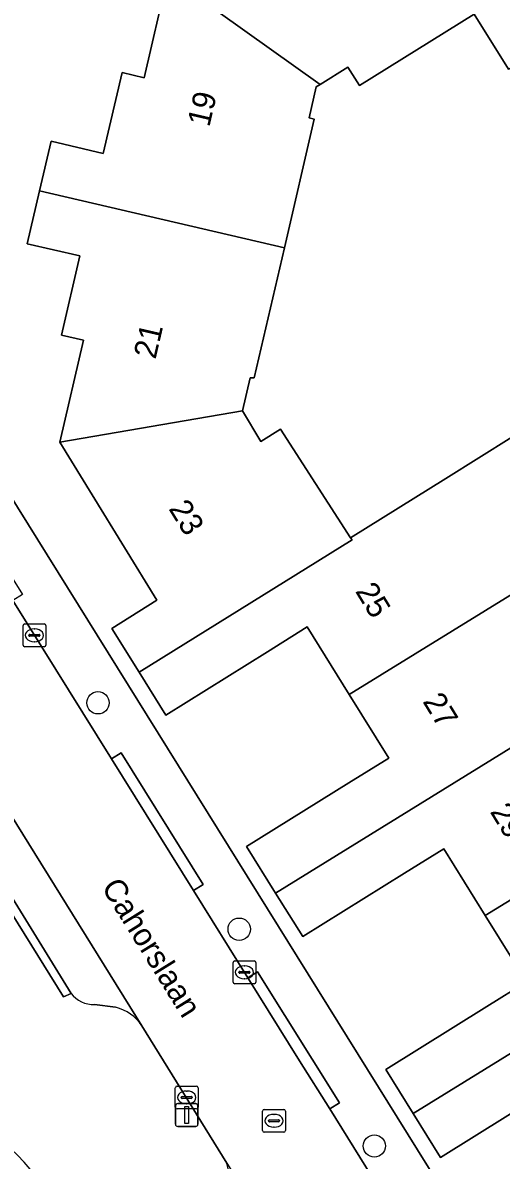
# Model space of a CAD drawing. Extents: x 157767 to 159172, y 387839 to 389425.
# Drawn here: x 158446.08 to 158467.07, y 387924.96 to 387974.82 of the extents above; entities that cross this region are included whole.
import ezdxf

# ---------------------------------------------------------------- set-up
doc = ezdxf.new("R2010")
doc.units = 0
for name, color, linetype in [('IMGEO_Boom', 7, 'Continuous'), ('IMGEO_Erf', 7, 'Continuous'), ('IMGEO_Groenvoorziening', 7, 'Continuous'), ('IMGEO_Kolk', 7, 'Continuous'), ('IMGEO_Lichtmast', 7, 'Continuous'), ('IMGEO_Openbare_ruimte_label', 7, 'Continuous'), ('IMGEO_Pand', 7, 'Continuous'), ('IMGEO_Pand_nummerreeks', 7, 'Continuous'), ('IMGEO_Parkeervlak_open', 7, 'Continuous'), ('IMGEO_Rijbaan_lokaal_open', 7, 'Continuous'), ('IMGEO_Rioolput', 7, 'Continuous'), ('IMGEO_Voetpad_open', 7, 'Continuous')]:
    doc.layers.add(name, color=color, linetype=linetype)

msp = doc.modelspace()

# ---------------------------------------------------------------- linework, layer by layer
at = {"layer": 'IMGEO_Boom'}
for centre in [(158449.378, 387945.013), (158455.572, 387935.087), (158461.501, 387925.585)]:
    msp.add_circle(centre, 0.489, dxfattribs=at)
at = {"layer": 'IMGEO_Erf'}
for points in [[(158448.579, 387964.602), (158446.275, 387965.138), (158446.814, 387967.458), (158447.318, 387969.628), (158449.61, 387969.095), (158450.434, 387972.639), (158451.397, 387972.415), (158452.411, 387976.774), (158452.509, 387976.838), (158459.229, 387981.189), (158457.961, 387983.225), (158439.194, 387971.552)], [(158467.381, 387972.796), (158465.877, 387975.202), (158460.842, 387972.067), (158460.34, 387972.872), (158459.127, 387972.116), (158458.953, 387972.008), (158458.638, 387970.655), (158458.866, 387970.602), (158457.554, 387964.961), (158456.229, 387959.261), (158456.053, 387959.255), (158455.719, 387957.819), (158456.527, 387956.474), (158457.389, 387957.01), (158460.458, 387952.25), (158464.629, 387954.847), (158467.535, 387956.657)], [(158437.958, 387966.246), (158481.823, 387895.818)], [(158468.831, 387927.847), (158464.397, 387925.086), (158463.201, 387927.007), (158461.998, 387928.939), (158466.44, 387931.706), (158468.175, 387932.786), (158466.367, 387935.69), (158464.544, 387938.617), (158462.824, 387937.546), (158458.356, 387934.763), (158457.17, 387936.667), (158455.897, 387938.712), (158460.374, 387941.5), (158462.129, 387942.593), (158460.391, 387945.383), (158458.552, 387948.336), (158456.811, 387947.252), (158452.354, 387944.476), (158451.184, 387946.354), (158449.987, 387948.276), (158451.965, 387949.508), (158447.698, 387956.443), (158448.735, 387960.904), (158447.772, 387961.128), (158448.579, 387964.602)]]:
    msp.add_lwpolyline(points, dxfattribs=at)
at = {"layer": 'IMGEO_Groenvoorziening'}
for points in [[(158448.198, 387932.275), (158447.868, 387932.128), (158432.012, 387957.61), (158429.442, 387956.032), (158425.712, 387954.443), (158422.465, 387953.545), (158421.291, 387953.13), (158420.116, 387952.094), (158419.978, 387950.574), (158420.047, 387949.469), (158418.319, 387947.093), (158426.944, 387933.867)], [(158450.152, 387931.664), (158449.224, 387931.789)], [(158454.886, 387922.79), (158455.16, 387923.484), (158455.184, 387924.168), (158455.028, 387924.834), (158451.306, 387930.857)]]:
    msp.add_lwpolyline(points, dxfattribs=at)
for centre, radius, start, end in [((158449.164, 387932.988), 1.2, 216.4323, 272.8754), ((158449.664, 387929.737), 1.988, 34.2912, 75.7781), ((158440.819, 387920.151), 7.115, 31.6126, 84.7108), ((158440.819, 387920.151), 7.115, 31.6126, 84.7108)]:
    msp.add_arc(centre, radius, start, end, dxfattribs=at)
at = {"layer": 'IMGEO_Kolk'}
for p, q in [((158446.164, 387948.471), (158447.016, 387948.471)), ((158446.089, 387947.545), (158446.089, 387948.397)), ((158446.348, 387947.965), (158446.348, 387947.977)), ((158446.786, 387947.928), (158446.388, 387947.928)), ((158446.391, 387948.014), (158446.789, 387948.014)), ((158446.577, 387948.251), (158446.602, 387948.251)), ((158446.832, 387947.977), (158446.832, 387947.965)), ((158447.09, 387948.397), (158447.09, 387947.545)), ((158447.016, 387947.471), (158446.164, 387947.471)), ((158446.6, 387947.691), (158446.575, 387947.691)), ((158455.301, 387932.772), (158455.301, 387933.624)), ((158455.376, 387933.698), (158456.228, 387933.698)), ((158455.789, 387933.478), (158455.814, 387933.478)), ((158456.302, 387933.624), (158456.302, 387932.772)), ((158455.56, 387933.192), (158455.56, 387933.204)), ((158455.998, 387933.155), (158455.6, 387933.155)), ((158455.603, 387933.241), (158456.001, 387933.241)), ((158456.044, 387933.204), (158456.044, 387933.192)), ((158456.228, 387932.698), (158455.376, 387932.698)), ((158455.812, 387932.918), (158455.787, 387932.918)), ((158452.77, 387927.287), (158452.77, 387928.139)), ((158452.845, 387928.213), (158453.697, 387928.213)), ((158453.258, 387927.993), (158453.283, 387927.993)), ((158453.771, 387928.139), (158453.771, 387927.287)), ((158453.029, 387927.707), (158453.029, 387927.719)), ((158453.467, 387927.67), (158453.069, 387927.67)), ((158453.072, 387927.756), (158453.47, 387927.756)), ((158453.513, 387927.719), (158453.513, 387927.707)), ((158453.697, 387927.213), (158452.845, 387927.213)), ((158453.281, 387927.433), (158453.256, 387927.433))]:
    msp.add_line(p, q, dxfattribs=at)
for points in [[(158446.164, 387948.471), (158447.016, 387948.471)], [(158446.089, 387947.545), (158446.089, 387948.397)], [(158447.09, 387948.397), (158447.09, 387947.545)], [(158447.016, 387947.471), (158446.164, 387947.471)], [(158455.301, 387932.772), (158455.301, 387933.624)], [(158455.376, 387933.698), (158456.228, 387933.698)], [(158456.302, 387933.624), (158456.302, 387932.772)], [(158456.228, 387932.698), (158455.376, 387932.698)], [(158452.77, 387927.287), (158452.77, 387928.139)], [(158452.845, 387928.213), (158453.697, 387928.213)], [(158453.771, 387928.139), (158453.771, 387927.287)], [(158453.697, 387927.213), (158452.845, 387927.213)]]:
    msp.add_lwpolyline(points, dxfattribs=at)
for centre, radius, start, end in [((158446.166, 387948.395), 0.0765, 91.552, 178.448), ((158446.166, 387948.395), 0.0765, 91.552, 178.448), ((158447.014, 387948.395), 0.0765, 1.552, 88.448), ((158447.014, 387948.395), 0.0765, 1.552, 88.448), ((158446.388, 387947.974), 0.0403, 85.8775, 175.7526), ((158446.385, 387947.964), 0.0366, 178.938, 274.7102), ((158446.789, 387947.971), 0.043, 264.8664, 352.4533), ((158446.793, 387947.976), 0.0386, 1.7309, 96.639), ((158446.166, 387947.547), 0.0765, 181.552, 268.448), ((158446.166, 387947.547), 0.0765, 181.552, 268.448), ((158447.014, 387947.547), 0.0765, 271.552, 358.448), ((158447.014, 387947.547), 0.0765, 271.552, 358.448), ((158455.378, 387933.622), 0.0765, 91.552, 178.448), ((158455.378, 387933.622), 0.0765, 91.552, 178.448), ((158456.226, 387933.622), 0.0765, 1.552, 88.448), ((158456.226, 387933.622), 0.0765, 1.552, 88.448), ((158455.6, 387933.201), 0.0403, 85.8775, 175.7526), ((158455.597, 387933.191), 0.0366, 178.938, 274.7102), ((158456.001, 387933.198), 0.043, 264.8664, 352.4533), ((158456.005, 387933.203), 0.0386, 1.7309, 96.639), ((158455.378, 387932.774), 0.0765, 181.552, 268.448), ((158455.378, 387932.774), 0.0765, 181.552, 268.448), ((158456.226, 387932.774), 0.0765, 271.552, 358.448), ((158456.226, 387932.774), 0.0765, 271.552, 358.448), ((158452.847, 387928.137), 0.0765, 91.552, 178.448), ((158452.847, 387928.137), 0.0765, 91.552, 178.448), ((158453.695, 387928.137), 0.0765, 1.552, 88.448), ((158453.695, 387928.137), 0.0765, 1.552, 88.448), ((158453.069, 387927.716), 0.0403, 85.8775, 175.7526), ((158453.066, 387927.706), 0.0366, 178.938, 274.7102), ((158453.47, 387927.713), 0.043, 264.8664, 352.4533), ((158453.474, 387927.718), 0.0386, 1.7309, 96.639), ((158452.847, 387927.289), 0.0765, 181.552, 268.448), ((158452.847, 387927.289), 0.0765, 181.552, 268.448), ((158453.695, 387927.289), 0.0765, 271.552, 358.448), ((158453.695, 387927.289), 0.0765, 271.552, 358.448)]:
    msp.add_arc(centre, radius, start, end, dxfattribs=at)
for centre, major_axis, ratio, start_param, end_param in [((158446.576, 387947.971), (-0.387, 0.002), 0.722429, 4.712389, 7.853982), ((158446.601, 387947.971), (-0.39, 0.002), 0.717154, 1.570796, 4.712389), ((158455.788, 387933.198), (-0.387, 0.002), 0.722429, 4.712389, 7.853982), ((158455.813, 387933.198), (-0.39, 0.002), 0.717154, 1.570796, 4.712389), ((158453.257, 387927.713), (-0.387, 0.002), 0.722429, 4.712389, 7.853982), ((158453.282, 387927.713), (-0.39, 0.002), 0.717154, 1.570796, 4.712389)]:
    msp.add_ellipse(centre, major_axis=major_axis, ratio=ratio, start_param=start_param, end_param=end_param, dxfattribs=at)
at = {"layer": 'IMGEO_Lichtmast'}
for p, q in [((158452.773, 387926.543), (158452.773, 387927.343)), ((158452.773, 387927.343), (158452.773, 387926.543)), ((158452.873, 387927.443), (158453.663, 387927.443)), ((158453.663, 387927.443), (158452.873, 387927.443)), ((158453.763, 387927.343), (158453.763, 387926.543)), ((158453.763, 387926.543), (158453.763, 387927.343)), ((158453.663, 387926.443), (158452.873, 387926.443)), ((158452.873, 387926.443), (158453.663, 387926.443))]:
    msp.add_line(p, q, dxfattribs=at)
msp.add_lwpolyline([(158453.193, 387927.318), (158453.343, 387927.318), (158453.343, 387926.568), (158453.193, 387926.568), (158453.193, 387927.318)], dxfattribs=at)
for centre, start, end in [((158452.873, 387927.343), 90, 180), ((158452.873, 387927.343), 90, 180), ((158453.663, 387927.343), 0, 90), ((158453.663, 387927.343), 360, 90), ((158452.873, 387926.543), 180, 270), ((158452.873, 387926.543), 180, 270), ((158453.663, 387926.543), 270, 0), ((158453.663, 387926.543), 270, 0)]:
    msp.add_arc(centre, 0.1, start, end, dxfattribs=at)
at = {"layer": 'IMGEO_Pand'}
for points in [[(158460.011, 387984.502), (158465.877, 387975.202), (158467.381, 387972.796), (158472.575, 387976.03), (158476.683, 387969.434), (158476.789, 387969.5), (158471.03, 387978.74), (158470.53, 387978.44), (158468.77, 387981.42), (158471.197, 387982.861), (158470.284, 387984.327), (158467.647, 387988.562), (158465.137, 387986.999), (158466.041, 387985.547), (158463.067, 387983.695), (158461.851, 387985.648)], [(158459.127, 387972.116), (158460.34, 387972.872), (158460.842, 387972.067), (158465.877, 387975.202), (158460.011, 387984.502), (158457.961, 387983.225), (158459.229, 387981.189), (158452.509, 387976.838)], [(158459.127, 387972.116), (158452.509, 387976.838), (158452.411, 387976.774), (158451.397, 387972.415), (158450.434, 387972.639), (158449.61, 387969.095), (158447.318, 387969.628), (158446.814, 387967.458), (158457.554, 387964.961), (158458.866, 387970.602), (158458.638, 387970.655), (158458.953, 387972.008)], [(158457.554, 387964.961), (158446.814, 387967.458), (158446.275, 387965.138), (158448.579, 387964.602), (158447.772, 387961.128), (158448.735, 387960.904), (158447.698, 387956.443), (158455.719, 387957.819), (158456.053, 387959.255), (158456.229, 387959.261)], [(158451.184, 387946.354), (158460.52, 387952.15), (158460.458, 387952.25), (158457.389, 387957.01), (158456.527, 387956.474), (158455.719, 387957.819), (158447.698, 387956.443), (158451.965, 387949.508), (158449.987, 387948.276)], [(158460.391, 387945.383), (158467.83, 387949.95), (158470.624, 387951.696), (158467.535, 387956.657), (158464.629, 387954.847), (158460.458, 387952.25), (158460.52, 387952.15), (158451.184, 387946.354), (158452.354, 387944.476), (158456.811, 387947.252), (158458.552, 387948.336)], [(158460.391, 387945.383), (158462.129, 387942.593), (158460.374, 387941.5), (158455.897, 387938.712), (158457.17, 387936.667), (158470.85, 387945.12), (158474.168, 387947.177), (158471.149, 387952.025), (158470.624, 387951.696), (158467.83, 387949.95)], [(158466.367, 387935.69), (158473.88, 387940.29), (158477.181, 387942.339), (158474.168, 387947.177), (158470.85, 387945.12), (158457.17, 387936.667), (158458.356, 387934.763), (158462.824, 387937.546), (158464.544, 387938.617)], [(158479.28, 387936.937), (158480.192, 387937.504), (158477.181, 387942.339), (158473.88, 387940.29), (158466.367, 387935.69), (158468.175, 387932.786), (158466.44, 387931.706), (158461.998, 387928.939), (158463.201, 387927.007), (158476.9, 387935.46)], [(158479.28, 387936.937), (158476.9, 387935.46), (158463.201, 387927.007), (158464.397, 387925.086), (158468.831, 387927.847), (158470.584, 387928.938), (158472.4, 387926.022), (158479.93, 387930.63), (158482.291, 387932.102)]]:
    msp.add_lwpolyline(points, close=True, dxfattribs=at)
at = {"layer": 'IMGEO_Parkeervlak_open'}
for points in [[(158451.306, 387930.857), (158432.322, 387961.384)], [(158432.467, 387959.286), (158432.221, 387958.553), (158432.403, 387957.887), (158448.198, 387932.275)], [(158449.224, 387931.789), (158450.152, 387931.664)]]:
    msp.add_lwpolyline(points, dxfattribs=at)
for centre, radius, start, end in [((158449.164, 387932.988), 1.2, 216.4323, 272.8754), ((158449.664, 387929.737), 1.988, 34.2912, 75.7781)]:
    msp.add_arc(centre, radius, start, end, dxfattribs=at)
at = {"layer": 'IMGEO_Rijbaan_lokaal_open'}
msp.add_lwpolyline([(158469.476, 387911.327), (158465.544, 387917.612), (158461.921, 387923.403), (158459.54, 387927.209), (158458.222, 387929.315), (158455.954, 387932.952), (158453.564, 387936.785), (158449.963, 387942.559), (158445.639, 387949.493), (158443.616, 387952.733), (158439.405, 387959.476), (158437.407, 387962.677), (158435.842, 387965.183), (158431.557, 387962.568), (158432.322, 387961.384), (158451.306, 387930.857), (158455.028, 387924.834), (158474.377, 387894.016)], dxfattribs=at)
at = {"layer": 'IMGEO_Rioolput'}
for p, q in [((158456.597, 387926.264), (158456.597, 387927.116)), ((158456.672, 387927.19), (158457.524, 387927.19)), ((158457.085, 387926.97), (158457.11, 387926.97)), ((158457.598, 387927.116), (158457.598, 387926.264)), ((158456.856, 387926.684), (158456.856, 387926.696)), ((158457.294, 387926.647), (158456.896, 387926.647)), ((158456.899, 387926.733), (158457.297, 387926.733)), ((158457.34, 387926.696), (158457.34, 387926.684)), ((158457.524, 387926.19), (158456.672, 387926.19)), ((158457.108, 387926.41), (158457.083, 387926.41))]:
    msp.add_line(p, q, dxfattribs=at)
for points in [[(158456.597, 387926.264), (158456.597, 387927.116)], [(158456.672, 387927.19), (158457.524, 387927.19)], [(158457.598, 387927.116), (158457.598, 387926.264)], [(158457.524, 387926.19), (158456.672, 387926.19)]]:
    msp.add_lwpolyline(points, dxfattribs=at)
for centre, radius, start, end in [((158456.674, 387927.114), 0.0765, 91.552, 178.448), ((158456.674, 387927.114), 0.0765, 91.552, 178.448), ((158457.522, 387927.114), 0.0765, 1.552, 88.448), ((158457.522, 387927.114), 0.0765, 1.552, 88.448), ((158456.896, 387926.693), 0.0403, 85.8775, 175.7526), ((158456.893, 387926.683), 0.0366, 178.938, 274.7102), ((158457.297, 387926.69), 0.043, 264.8664, 352.4533), ((158457.301, 387926.695), 0.0386, 1.7309, 96.639), ((158456.674, 387926.266), 0.0765, 181.552, 268.448), ((158456.674, 387926.266), 0.0765, 181.552, 268.448), ((158457.522, 387926.266), 0.0765, 271.552, 358.448), ((158457.522, 387926.266), 0.0765, 271.552, 358.448)]:
    msp.add_arc(centre, radius, start, end, dxfattribs=at)
for centre, major_axis, ratio, start_param, end_param in [((158457.084, 387926.69), (-0.387, 0.002), 0.722429, 4.712389, 7.853982), ((158457.109, 387926.69), (-0.39, 0.002), 0.717154, 1.570796, 4.712389)]:
    msp.add_ellipse(centre, major_axis=major_axis, ratio=ratio, start_param=start_param, end_param=end_param, dxfattribs=at)
at = {"layer": 'IMGEO_Voetpad_open'}
msp.add_lwpolyline([(158481.823, 387895.818), (158437.958, 387966.246), (158435.842, 387965.183), (158437.407, 387962.677), (158437.832, 387962.939), (158439.83, 387959.738), (158439.405, 387959.476), (158443.616, 387952.733), (158444.04, 387952.995), (158446.064, 387949.755), (158445.639, 387949.493), (158449.963, 387942.559), (158450.388, 387942.821), (158453.989, 387937.047), (158453.564, 387936.785), (158455.954, 387932.952), (158456.379, 387933.214), (158459.965, 387927.471), (158459.54, 387927.209), (158461.921, 387923.403), (158462.345, 387923.665), (158465.969, 387917.874), (158465.544, 387917.612), (158469.476, 387911.327)], dxfattribs=at)
for points in [[(158432.403, 387957.887), (158432.012, 387957.61), (158447.868, 387932.128), (158448.198, 387932.275)], [(158453.564, 387936.785), (158453.989, 387937.047), (158450.388, 387942.821), (158449.963, 387942.559)], [(158459.54, 387927.209), (158459.965, 387927.471), (158456.379, 387933.214), (158455.954, 387932.952), (158458.222, 387929.315)]]:
    msp.add_lwpolyline(points, close=True, dxfattribs=at)

# ---------------------------------------------------------------- texts
at = {"layer": 'IMGEO_Openbare_ruimte_label'}
msp.add_text('Cahorslaan', height=1, rotation=301.8778, dxfattribs=at).set_placement((158449.504, 387936.933))
at = {"layer": 'IMGEO_Pand_nummerreeks'}
for s, rotation, p in [('19', 76.949, (158454.258, 387970.219)), ('21', 76.949, (158451.9, 387960.044)), ('23', 301.9139, (158452.453, 387953.522)), ('25', 301.4391, (158460.641, 387949.906)), ('27', 301.4391, (158463.596, 387945.073)), ('29', 301.4391, (158466.551, 387940.239))]:
    msp.add_text(s, height=1, rotation=rotation, dxfattribs=at).set_placement(p)

doc.saveas('drawing.dxf')
